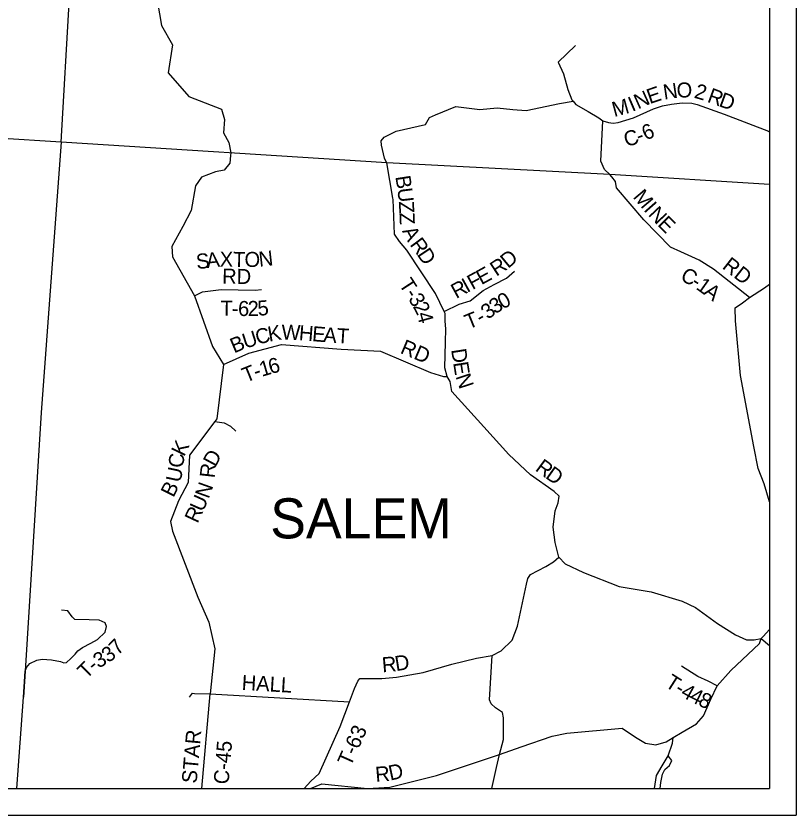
# Model space of a CAD drawing. Extents: x -15 to 405, y -40 to 87.
# Drawn here: x 27.116 to 30.065, y -34.096 to -31.075 of the extents above; entities that cross this region are included whole.
import ezdxf

# ---------------------------------------------------------------- set-up
doc = ezdxf.new("R2010")
doc.units = 0
for name, color, linetype in [('GM_P_State_Location', 7, 'Continuous'), ('GM_X_County_Road_Text', 7, 'Continuous'), ('GM_X_Interchange_Ramps', 7, 'Continuous'), ('GM_X_Minor_Lake', 7, 'Continuous'), ('GM_X_Minor_River', 7, 'Continuous'), ('GM_X_Rail_Line', 7, 'Continuous'), ('GM_X_State_Route', 7, 'Continuous'), ('GM_X_Township', 7, 'Continuous'), ('GM_X_Township_Text', 7, 'Continuous')]:
    doc.layers.add(name, color=color, linetype=linetype)

msp = doc.modelspace()

# ---------------------------------------------------------------- linework, layer by layer
at = {"layer": 'GM_P_State_Location'}
msp.add_line((29.9334, -33.4283), (29.9652, -33.4552), dxfattribs=at)
for points in [[(27.7555, -30.5561), (27.6916, -30.8844), (27.6441, -30.9766), (27.6664, -31.1108), (27.7083, -31.1835), (27.6916, -31.2897), (27.7698, -31.3791), (27.8928, -31.4266), (27.9039, -31.4658), (27.9012, -31.5161), (27.9207, -31.5524), (27.9279, -31.5925), (27.927, -31.6023)], [(29.1662, -31.2499), (29.2317, -31.1862)], [(28.5094, -31.6132), (28.5092, -31.6128), (28.498, -31.5637), (28.4965, -31.5473), (28.5084, -31.5329), (28.554, -31.5098), (28.6642, -31.4848), (28.6793, -31.4588), (28.7027, -31.448), (28.7796, -31.4173), (28.8704, -31.4278), (28.9356, -31.4217), (28.9945, -31.4281), (29.0451, -31.4317), (29.1709, -31.4054), (29.2221, -31.397)], [(27.927, -31.6023), (27.9243, -31.6312), (27.9035, -31.6574), (27.8704, -31.6642), (27.8173, -31.6838), (27.795, -31.7173), (27.7782, -31.8095), (27.7475, -31.871), (27.7055, -31.9465), (27.7083, -31.9856), (27.7909, -32.1328), (27.8592, -32.3238), (27.9006, -32.3923), (27.876, -32.5977), (27.8684, -32.6075), (27.7726, -32.7347), (27.767, -32.8381), (27.7307, -32.908), (27.7, -32.9862), (27.7083, -33.0226), (27.8033, -33.2713), (27.8453, -33.3664), (27.8676, -33.467), (27.8505, -33.6375)], [(28.5417, -31.7682), (28.5415, -31.7637), (28.5185, -31.6301), (28.5094, -31.6132)], [(29.1688, -33.1208), (29.1548, -33.0655), (29.1475, -33.0069), (29.155, -32.9454), (29.1661, -32.9147), (29.1698, -32.8904), (29.1513, -32.8727), (29.0619, -32.8089), (28.979, -32.7331), (28.8847, -32.6274), (28.7637, -32.4941), (28.7577, -32.4571), (28.7468, -32.4376), (28.7377, -32.4044), (28.7404, -32.3079), (28.7409, -32.2573), (28.7382, -32.2287), (28.7393, -32.1998), (28.7352, -32.1914), (28.7021, -32.1237), (28.5937, -31.9601), (28.5666, -31.9279), (28.5472, -31.8999), (28.5417, -31.7687), (28.5417, -31.7682)], [(28.7352, -32.1914), (28.7923, -32.1636), (28.8331, -32.1522), (28.8827, -32.1125), (28.9245, -32.0902), (28.9707, -32.0656), (29.0011, -32.0398)], [(27.7909, -32.1328), (27.8216, -32.1172), (27.8913, -32.1085), (28.0199, -32.1114), (28.0447, -32.1087)], [(27.9006, -32.3923), (27.9966, -32.35), (28.1199, -32.3164), (28.3454, -32.3349), (28.4941, -32.3423), (28.6835, -32.4221), (28.7324, -32.4378), (28.7468, -32.4376)], [(27.8684, -32.6075), (27.903, -32.6132), (27.9268, -32.6257), (27.9471, -32.6442)], [(27.1505, -33.5516), (27.1555, -33.5379), (27.1681, -33.5226), (27.1947, -33.51), (27.2156, -33.5058), (27.2506, -33.5086), (27.2841, -33.5156), (27.2967, -33.5198), (27.3078, -33.5184), (27.3232, -33.5044), (27.34, -33.4876), (27.3498, -33.475), (27.3679, -33.4625), (27.3987, -33.4457), (27.4238, -33.4317), (27.4531, -33.4038), (27.4587, -33.3828), (27.4531, -33.3688), (27.4308, -33.3591), (27.3931, -33.3577), (27.3386, -33.3563), (27.3288, -33.3465), (27.312, -33.3241), (27.2883, -33.3213)], [(28.9149, -33.9955), (28.933, -33.9157), (28.9439, -33.8661), (28.9597, -33.8102), (28.9599, -33.728), (28.9556, -33.7078), (28.9287, -33.69), (28.9129, -33.6746), (28.9066, -33.6605), (28.9163, -33.492)], [(27.1195, -33.9955), (27.1446, -33.6501), (27.1505, -33.5516)], [(29.7676, -33.6073), (29.7333, -33.5889), (29.6936, -33.5721), (29.632, -33.5326)], [(27.7723, -33.6494), (27.7834, -33.6347), (27.7911, -33.6361), (27.8505, -33.6375)], [(28.2057, -33.9955), (28.2306, -33.9677), (28.2621, -33.9384), (28.3422, -33.7609), (28.3774, -33.6677)], [(29.5515, -33.9955), (29.5546, -33.9728), (29.5606, -33.9413), (29.5688, -33.9236), (29.5865, -33.9086), (29.5955, -33.8896), (29.5824, -33.8712)]]:
    msp.add_lwpolyline(points, dxfattribs=at)
at = {"layer": 'GM_X_Interchange_Ramps'}
msp.add_line((27.2876, -31.5517), (27.2116, -32.5736), dxfattribs=at)
at = {"layer": 'GM_X_Rail_Line'}
for p, q in [((27.2876, -31.5517), (27.3203, -30.9756)), ((27.2876, -31.5517), (26.2696, -31.4887)), ((28.5185, -31.6301), (27.2876, -31.5517)), ((29.3611, -31.6738), (28.5185, -31.6301)), ((29.9652, -31.7118), (29.3611, -31.6738)), ((27.2116, -32.5736), (27.1505, -33.5516))]:
    msp.add_line(p, q, dxfattribs=at)
at = {"layer": 'GM_X_State_Route'}
for p in [(27.1505, -33.5516), (27.1195, -33.9955)]:
    msp.add_line(p, (27.1446, -33.6501), dxfattribs=at)
at = {"layer": 'GM_X_Township'}
for p, q in [((30.0652, -27.0955), (30.0652, -34.0955)), ((29.9652, -27.1955), (29.9652, -33.9955)), ((23.1652, -33.9955), (29.9652, -33.9955)), ((23.0652, -34.0955), (30.0652, -34.0955))]:
    msp.add_line(p, q, dxfattribs=at)
at = {"layer": 'GM_X_Township_Text'}
for points in [[(29.1662, -31.2499), (29.1865, -31.293), (29.2028, -31.3524), (29.2178, -31.3923), (29.2221, -31.397), (29.2332, -31.4088), (29.2794, -31.4364), (29.3196, -31.4595), (29.3347, -31.4706)], [(29.3347, -31.4706), (29.3567, -31.4779), (29.3745, -31.4795), (29.3928, -31.4774), (29.4511, -31.4599), (29.5266, -31.4254), (29.5598, -31.4148), (29.5947, -31.4079), (29.6342, -31.4036), (29.6707, -31.4038), (29.6913, -31.4088), (29.7936, -31.4464), (29.9612, -31.5101), (29.9652, -31.5128)], [(29.3683, -31.6824), (29.3611, -31.6738), (29.3413, -31.6545), (29.3273, -31.6233), (29.3347, -31.4706)], [(29.8896, -32.139), (29.7534, -32.0321), (29.6985, -31.9976), (29.6299, -31.966), (29.5905, -31.9487), (29.4904, -31.8459), (29.3867, -31.724), (29.383, -31.6999), (29.3683, -31.6824)], [(29.8896, -32.139), (29.9457, -32.1029), (29.9652, -32.0885)], [(29.9652, -32.9113), (29.9444, -32.8435), (29.9215, -32.786), (29.9057, -32.7023), (29.855, -32.4333), (29.8369, -32.2268), (29.8357, -32.1778), (29.8632, -32.1594), (29.8896, -32.139)], [(27.8184, -33.9955), (27.8505, -33.6375), (28.3774, -33.6677), (28.3959, -33.6169), (28.409, -33.59), (28.4167, -33.5794), (28.4996, -33.5791), (28.5543, -33.5749), (28.6559, -33.5561), (28.7644, -33.5249), (28.8577, -33.5023), (28.9163, -33.492), (28.951, -33.4747), (28.9915, -33.4347), (29.0128, -33.3813), (29.0457, -33.223), (29.0508, -33.2017), (29.0612, -33.1862), (29.1199, -33.1562), (29.1477, -33.1385), (29.1688, -33.1208), (29.1929, -33.146), (29.2615, -33.1783), (29.3961, -33.232), (29.5176, -33.2513), (29.6348, -33.2866), (29.6856, -33.3113), (29.7681, -33.3714), (29.8362, -33.414), (29.8775, -33.4333), (29.9068, -33.4338), (29.9334, -33.4283)], [(29.53, -33.9955), (29.5375, -33.9457), (29.5586, -33.9101), (29.5824, -33.8712), (29.5983, -33.8241), (29.6011, -33.8028), (29.6343, -33.7825), (29.6885, -33.7502), (29.7153, -33.7203), (29.7431, -33.6578), (29.7676, -33.6073), (29.819, -33.5492), (29.9268, -33.4473), (29.9334, -33.4283), (29.9411, -33.4204), (29.9652, -33.3947)], [(28.2295, -33.9955), (28.2724, -33.9771), (28.4448, -33.9949), (28.5296, -33.9897), (28.7066, -33.9463), (28.9439, -33.8661), (29.0262, -33.8377), (29.1435, -33.797), (29.1983, -33.7859), (29.4075, -33.7675), (29.4582, -33.8016), (29.4965, -33.8235), (29.5348, -33.8302), (29.574, -33.8183), (29.6011, -33.8028)]]:
    msp.add_lwpolyline(points, dxfattribs=at)

# ---------------------------------------------------------------- texts
at = {"layer": 'GM_X_County_Road_Text'}
msp.add_text('SALEM', height=0.15152, rotation=0, dxfattribs=at).set_placement((28.0773, -33.0497))
at = {"layer": 'GM_X_Minor_Lake'}
for s, height, rotation, p in [('O', 0.0568, 2.1024, (29.6147, -31.3839)), ('E', 0.0568, 18.9703, (29.5123, -31.4082)), ('N', 0.0568, 8.4382, (29.5669, -31.3911)), ('2', 0.0568, 343.6472, (29.6773, -31.3831)), ('R', 0.0568, 339.9159, (29.7265, -31.3985)), ('I', 0.0568, 23.4091, (29.4458, -31.4377)), ('N', 0.0568, 24.1603, (29.468, -31.4281)), ('D', 0.0568, 339.8656, (29.7703, -31.4146)), ('M', 0.0568, 15.2362, (29.378, -31.4569)), ('C', 0.0568, 17.134, (29.4239, -31.5707)), ('6', 0.0568, 24.1155, (29.4974, -31.5462)), ('-', 0.0568, 20.3817, (29.4718, -31.5559)), ('M', 0.0568, 310.1195, (29.4463, -31.7598)), ('I', 0.0568, 311.3748, (29.4869, -31.808)), ('N', 0.0568, 313.2691, (29.5037, -31.827)), ('E', 0.0568, 314.6098, (29.5389, -31.8644)), ('RD', 0.05682, 321.9517, (29.783, -32.0266)), ('C', 0.0568, 332.344, (29.6244, -32.0718)), ('-', 0.0568, 328.0616, (29.6648, -32.0929)), ('1', 0.0568, 324.6239, (29.6838, -32.1047)), ('A', 0.0568, 322.4132, (29.7119, -32.1247)), ('R', 0.0568, 4.7006, (28.5019, -33.5562)), ('D', 0.0568, 9.22, (28.5532, -33.5518)), ('HALL', 0.05682, 356.6485, (27.9685, -33.6221)), ('STAR', 0.05682, 84.8784, (27.799, -33.9776)), ('C-45', 0.05682, 85.1793, (27.9197, -33.9811)), ('R', 0.0568, 4.5439, (28.4766, -33.9704)), ('D', 0.0568, 12.1325, (28.5311, -33.9655))]:
    msp.add_text(s, height=height, rotation=rotation, dxfattribs=at).set_placement(p)
at = {"layer": 'GM_X_Minor_River'}
for s, height, rotation, p in [('B', 0.0568, 279.0119, (28.5502, -31.6819)), ('U', 0.0568, 276.9362, (28.5575, -31.7275)), ('Z', 0.0568, 273.1644, (28.5634, -31.7761)), ('Z', 0.0568, 272.3578, (28.5658, -31.8183)), ('A', 0.0568, 298.0937, (28.5748, -31.8875)), ('R', 0.0568, 306.4686, (28.6031, -31.9392)), ('D', 0.0568, 303.8522, (28.6305, -31.9762)), ('S', 0.0568, 6.4517, (27.8003, -32.032)), ('A', 0.0568, 6.0656, (27.8383, -32.0277)), ('X', 0.0568, 359.4827, (27.8863, -32.0225)), ('T', 0.0568, 358.9114, (27.9362, -32.023)), ('O', 0.0568, 0.582, (27.9805, -32.0238)), ('N', 0.0568, 6.2776, (28.0366, -32.0229)), ('D', 0.0568, 39.5573, (28.9765, -32.0312)), ('R', 0.0568, 33.6486, (28.9325, -32.0609)), ('RD', 0.05682, 359.0128, (27.8952, -32.0863)), ('F', 0.0568, 28.7751, (28.8419, -32.1112)), ('E', 0.0568, 28.7995, (28.8756, -32.0927)), ('T', 0.0568, 303.0357, (28.562, -32.0891)), ('R', 0.0568, 28.7727, (28.7806, -32.1449)), ('I', 0.0568, 28.7724, (28.8215, -32.1224)), ('-', 0.0568, 302.7699, (28.5852, -32.1247)), ('3', 0.0568, 301.7715, (28.5977, -32.1441)), ('3', 0.0568, 32.274, (28.9274, -32.2031)), ('0', 0.0568, 28.9174, (28.9562, -32.1849)), ('T', 0.0568, 359.5586, (27.8896, -32.2078)), ('6', 0.0568, 359.0041, (27.9554, -32.2086)), ('2', 0.0568, 1.0757, (27.9926, -32.2092)), ('5', 0.0568, 4.7587, (28.0316, -32.2083)), ('2', 0.0568, 297.7451, (28.6156, -32.1729)), ('3', 0.0568, 38.3115, (28.9012, -32.2239)), ('-', 0.0568, 358.8993, (27.932, -32.2081)), ('4', 0.0568, 285.4601, (28.6307, -32.2009)), ('T', 0.0568, 22.2351, (28.8267, -32.2604)), ('-', 0.0568, 30.0698, (28.8737, -32.2406)), ('C', 0.0568, 15.1149, (28.0294, -32.3182)), ('K', 0.0568, 9.951, (28.0731, -32.3063)), ('W', 0.0568, 358.3923, (28.1193, -32.2979)), ('H', 0.0568, 355.3613, (28.1843, -32.2997)), ('E', 0.0568, 355.364, (28.2342, -32.3038)), ('A', 0.0568, 355.4759, (28.2766, -32.3072)), ('T', 0.0568, 356.5429, (28.3276, -32.3112)), ('B', 0.0568, 22.8683, (27.9406, -32.3507)), ('U', 0.0568, 17.4897, (27.9823, -32.3331)), ('RD', 0.05682, 337.1891, (28.5656, -32.3479)), ('D', 0.0568, 278.9006, (28.7611, -32.3362)), ('1', 0.0568, 16.3643, (28.0454, -32.439)), ('6', 0.0568, 15.4121, (28.0787, -32.4292)), ('E', 0.0568, 278.9567, (28.7688, -32.3856)), ('T', 0.0568, 22.0823, (27.9852, -32.4618)), ('-', 0.0568, 18.2362, (28.0237, -32.4462)), ('N', 0.0568, 288.0814, (28.7777, -32.4371)), ('K', 0.0568, 64.0084, (27.7515, -32.7431)), ('C', 0.0568, 85.2019, (27.749, -32.7843)), ('D', 0.0568, 61.7258, (27.8703, -32.7825)), ('R', 0.0568, 83.5329, (27.8667, -32.8234)), ('R', 0.0568, 323.6797, (29.0761, -32.7911)), ('U', 0.0568, 78.1134, (27.7376, -32.8408)), ('D', 0.0568, 324.6323, (29.1146, -32.8193)), ('B', 0.0568, 63.3983, (27.7115, -32.8976)), ('N', 0.0568, 70.2891, (27.8448, -32.9022)), ('U', 0.0568, 65.812, (27.8225, -32.9523)), ('R', 0.0568, 64.9781, (27.8024, -32.9954)), ('7', 0.0568, 45.4508, (27.5017, -33.4943)), ('3', 0.0568, 34.9924, (27.4645, -33.5217)), ('3', 0.0568, 28.2782, (27.4275, -33.5421)), ('T', 0.0568, 44.1742, (27.3821, -33.5838)), ('-', 0.0568, 38.5172, (27.4114, -33.5551)), ('T', 0.0568, 327.4904, (29.5665, -33.6076)), ('-', 0.0568, 328.5384, (29.6033, -33.631)), ('4', 0.0568, 330.9167, (29.6255, -33.6445)), ('4', 0.0568, 333.5086, (29.6585, -33.6628)), ('8', 0.0568, 335.3703, (29.6917, -33.6793)), ('T-63', 0.05682, 65.9761, (28.3814, -33.9148))]:
    msp.add_text(s, height=height, rotation=rotation, dxfattribs=at).set_placement(p)

doc.saveas('drawing.dxf')
